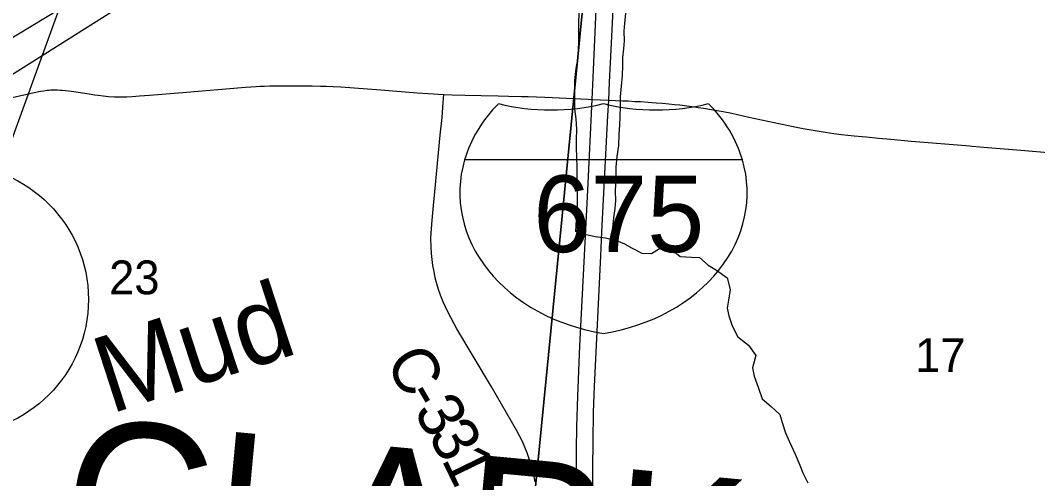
# Model space of a CAD drawing. Extents: x 0 to 1134, y 0 to 440.
# Drawn here: x 249.55 to 287.26, y 86.55 to 103.55 of the extents above; entities that cross this region are included whole.
import ezdxf

# ---------------------------------------------------------------- set-up
doc = ezdxf.new("R2010")
doc.units = 0
for name, color, linetype in [('GM_X_County_Road', 7, 'Continuous'), ('GM_X_County_Road_Text', 7, 'Continuous'), ('GM_X_County_Text', 7, 'Continuous'), ('GM_X_Interstate_Location', 7, 'Continuous'), ('GM_X_Interstate_Route', 7, 'Continuous'), ('GM_X_Interstate_Shield', 7, 'Continuous'), ('GM_X_Minor_River', 7, 'Continuous'), ('GM_X_Minor_River_Text', 7, 'Continuous'), ('GM_X_Rail_Line', 7, 'Continuous'), ('GM_X_Section', 7, 'Continuous'), ('GM_X_Section_Text', 7, 'Continuous'), ('SH_Data', 7, 'Continuous'), ('SH_Masking', 7, 'Continuous'), ('SH_Text', 7, 'Continuous')]:
    doc.layers.add(name, color=color, linetype=linetype)

msp = doc.modelspace()

# ---------------------------------------------------------------- linework, layer by layer
at = {"layer": 'GM_X_County_Road'}
for points in [[(248.09, 100.419), (250.181, 100.896), (250.296, 100.915), (250.418, 100.936), (250.551, 100.952), (250.612, 100.958), (250.675, 100.964), (250.757, 100.968), (250.851, 100.968), (250.936, 100.965), (251.024, 100.961), (251.121, 100.953), (251.23, 100.943), (251.342, 100.93), (251.541, 100.905), (251.948, 100.842), (252.181, 100.806), (252.306, 100.785), (252.441, 100.765), (252.617, 100.742), (252.825, 100.719), (253.031, 100.708), (253.168, 100.704), (253.304, 100.708), (253.495, 100.713), (253.703, 100.724), (253.975, 100.742), (254.346, 100.77), (255.56, 100.875), (257.895, 101.063), (258.102, 101.077), (258.291, 101.09), (258.439, 101.102), (258.598, 101.108), (258.789, 101.115), (259.001, 101.119), (260.213, 101.116), (260.375, 101.113), (260.673, 101.11), (260.887, 101.102), (261.145, 101.09), (261.435, 101.074), (262.912, 100.965), (264.266, 100.863), (264.664, 100.835), (265.25, 100.8)], [(268.634, 86.436), (268.603, 86.62), (268.555, 86.832), (268.492, 87.068), (268.34, 87.505), (268.16, 87.932), (267.949, 88.344), (267.016, 89.952), (265.731, 92.112), (265.42, 92.686), (265.31, 92.922), (265.227, 93.111), (265.131, 93.35), (265.056, 93.561), (264.993, 93.771), (264.932, 93.998), (264.886, 94.23), (264.842, 94.457), (264.813, 94.677), (264.791, 94.897), (264.776, 95.139), (264.774, 95.482), (264.791, 95.809), (264.815, 96.134), (264.864, 96.674), (264.917, 97.189), (265.12, 99.283), (265.189, 99.944), (265.229, 100.5), (265.25, 100.8)], [(265.25, 100.8), (265.562, 100.787), (266.04, 100.772), (266.631, 100.759), (267.262, 100.747), (267.652, 100.738), (268.121, 100.724), (268.376, 100.718), (268.999, 100.696), (270.603, 100.622)], [(270.603, 100.622), (270.752, 100.615), (271.361, 100.586), (271.61, 100.57), (271.875, 100.562), (272.091, 100.556), (272.327, 100.542), (272.543, 100.531), (272.825, 100.514), (273.123, 100.491), (273.351, 100.474), (273.584, 100.451), (273.806, 100.428), (273.993, 100.408), (274.252, 100.374), (274.536, 100.334), (274.681, 100.317), (274.871, 100.289), (275.099, 100.252), (275.309, 100.215), (275.605, 100.161), (275.923, 100.099), (276.554, 99.961), (278.194, 99.609), (278.567, 99.536), (278.936, 99.467), (279.386, 99.4), (279.712, 99.351), (279.993, 99.318), (280.454, 99.266), (280.909, 99.221), (281.364, 99.18), (281.814, 99.14), (282.572, 99.071), (283.366, 99.003), (284.746, 98.886)], [(284.746, 98.886), (284.835, 98.879), (285.402, 98.831), (286.494, 98.743), (287.802, 98.636)]]:
    msp.add_lwpolyline(points, dxfattribs=at)
at = {"layer": 'GM_X_Interstate_Route'}
for points in [[(270.752, 100.615), (270.776, 101.148), (270.897, 103.942), (270.898, 103.972)], [(271.361, 100.586), (271.392, 101.25), (271.426, 101.964), (271.521, 103.933)], [(270.88, 77.09), (270.755, 77.996), (270.654, 78.844), (270.602, 79.297), (270.545, 79.839), (270.467, 80.591), (270.43, 80.952), (270.401, 81.341), (270.352, 81.904), (270.312, 82.458), (270.218, 84.392), (270.17, 85.977), (270.167, 87.637), (270.178, 88.473), (270.212, 89.611), (270.295, 91.477), (270.509, 95.784), (270.582, 97.248), (270.752, 100.615)], [(270.974, 81.862), (270.87, 83.441), (270.837, 84.195), (270.811, 85.011), (270.791, 85.523), (270.775, 85.973), (270.776, 86.427), (270.772, 87.044), (270.782, 87.818), (270.788, 88.248), (270.794, 88.691), (270.798, 89.021), (270.836, 89.963), (271.067, 94.814), (271.112, 95.701), (271.328, 100.017), (271.361, 100.586)]]:
    msp.add_lwpolyline(points, dxfattribs=at)
at = {"layer": 'GM_X_Interstate_Shield'}
msp.add_line((276.319, 98.369), (266.018, 98.369), dxfattribs=at)
msp.add_line((276.319, 98.369), (266.018, 98.369), dxfattribs=at)
for centre, start_param, end_param in [((272.5, 97.152), 2.47259, 2.911027), ((269.223, 105.55), 4.415841, 5.008937), ((273.114, 105.55), 4.415841, 5.008937), ((269.837, 97.152), 0.230566, 0.669003), ((272.5, 97.152), 2.911027, 4.511031), ((269.837, 97.152), 4.913747, 6.513751)]:
    msp.add_ellipse(centre, major_axis=(6.658, 0), ratio=0.8, start_param=start_param, end_param=end_param, dxfattribs=at)
at = {"layer": 'GM_X_Minor_River'}
for points in [[(271.517, 95.417), (271.518, 95.842), (271.546, 96.228), (271.607, 96.569), (271.622, 96.864), (271.615, 97.216), (271.632, 97.739), (271.637, 98.103), (271.676, 98.5), (271.738, 98.909), (271.754, 99.34), (271.769, 99.659), (271.784, 99.954), (271.801, 100.363), (271.794, 100.715), (271.833, 101.101), (271.872, 101.499), (271.888, 101.874), (271.891, 102.169), (271.918, 102.487), (271.944, 102.782), (271.937, 103.146), (271.964, 103.441), (272.042, 104.282)], [(270.149, 95.708), (270.162, 96.166), (270.188, 96.495), (270.203, 96.79), (270.207, 97.109), (270.189, 97.438), (270.196, 98.075), (270.179, 98.496), (270.171, 98.791), (270.164, 99.11), (270.18, 99.507), (270.151, 99.894), (270.11, 100.27), (270.103, 100.622), (270.107, 100.941), (270.1, 101.316), (270.151, 101.758), (270.212, 102.099), (270.239, 102.417), (270.255, 102.78), (270.258, 103.076), (270.252, 103.496), (270.281, 104.007)], [(270.257, 95.664), (270.857, 95.532), (271.242, 95.482), (271.649, 95.386), (271.942, 95.257), (272.235, 95.095), (272.595, 94.908), (272.947, 94.904), (273.244, 95.082), (273.585, 95.135), (274.011, 94.789), (274.43, 94.761), (274.725, 94.746), (275.05, 94.469), (275.354, 94.284), (275.747, 93.995), (275.867, 93.561), (275.805, 93.164), (275.756, 92.869), (275.809, 92.584), (275.941, 92.219), (276.151, 91.807), (276.544, 91.496), (276.812, 91.117), (276.693, 90.664), (276.757, 90.356), (276.899, 89.945), (277.053, 89.512), (277.389, 89.223), (277.703, 88.924), (277.79, 88.639), (277.91, 88.251), (278.065, 87.919), (278.275, 87.462), (278.451, 87.051), (278.561, 86.765), (278.738, 86.399)]]:
    msp.add_lwpolyline(points, dxfattribs=at)
at = {"layer": 'GM_X_Rail_Line'}
for points in [[(218.648, 83.037), (235.81, 94.775), (255.549, 106.729), (261.683, 110.193), (266.302, 112.35), (271.641, 114.346)], [(219.083, 82.528), (255.537, 105.523), (261.361, 108.742), (267.318, 112.049), (271.641, 114.346)]]:
    msp.add_lwpolyline(points, dxfattribs=at)
at = {"layer": 'GM_X_Section'}
for points in [[(239.744, 111.129), (270.808, 108.206), (267.778, 77.468), (236.861, 80.551)], [(270.808, 108.206), (299.553, 105.536), (296.601, 74.807), (267.778, 77.468)]]:
    msp.add_lwpolyline(points, close=True, dxfattribs=at)
at = {"layer": 'SH_Data'}
msp.add_line((254.141, 112.649), (247.077, 93.196), dxfattribs=at)
at = {"layer": 'SH_Masking'}
msp.add_circle((247.077, 93.196), 5, dxfattribs=at)
at = {"layer": 'SH_Text'}
msp.add_circle((247.077, 93.196), 5, dxfattribs=at)

# ---------------------------------------------------------------- texts
at = {"layer": 'GM_X_County_Road_Text'}
for s, rotation, p in [('C', 300.275, (263.049, 90.867)), ('-', 300.2716, (263.755, 89.658)), ('3', 300.2587, (264.107, 89.053)), ('3', 300.1793, (264.636, 88.147)), ('1', 295.9623, (265.149, 87.269))]:
    msp.add_text(s, height=1.705, rotation=rotation, dxfattribs=at).set_placement(p)
at = {"layer": 'GM_X_County_Text'}
msp.add_text('CLARK COUNTY', height=5.68182, rotation=354.6384, dxfattribs=at).set_placement((250.939, 83.193))
at = {"layer": 'GM_X_Interstate_Location'}
for s in ['-', '.', ',']:
    msp.add_text(s, height=0.00568, dxfattribs=at).set_placement((271.168, 96.369))
msp.add_text('675', height=0.00568, rotation=0, dxfattribs=at).set_placement((269.432, 95.193))
at = {"layer": 'GM_X_Interstate_Shield'}
msp.add_text('675', height=2.8409, dxfattribs=at).set_placement((268.565, 94.951))
at = {"layer": 'GM_X_Minor_River_Text'}
msp.add_text('Mud', height=2.8408, rotation=18.002, dxfattribs=at).set_placement((252.885, 88.941))
at = {"layer": 'GM_X_Section_Text'}
for s, p in [('23', (252.844, 93.386)), ('17', (282.719, 90.502))]:
    msp.add_text(s, height=1.2557, rotation=0, dxfattribs=at).set_placement(p)

doc.saveas('drawing.dxf')
